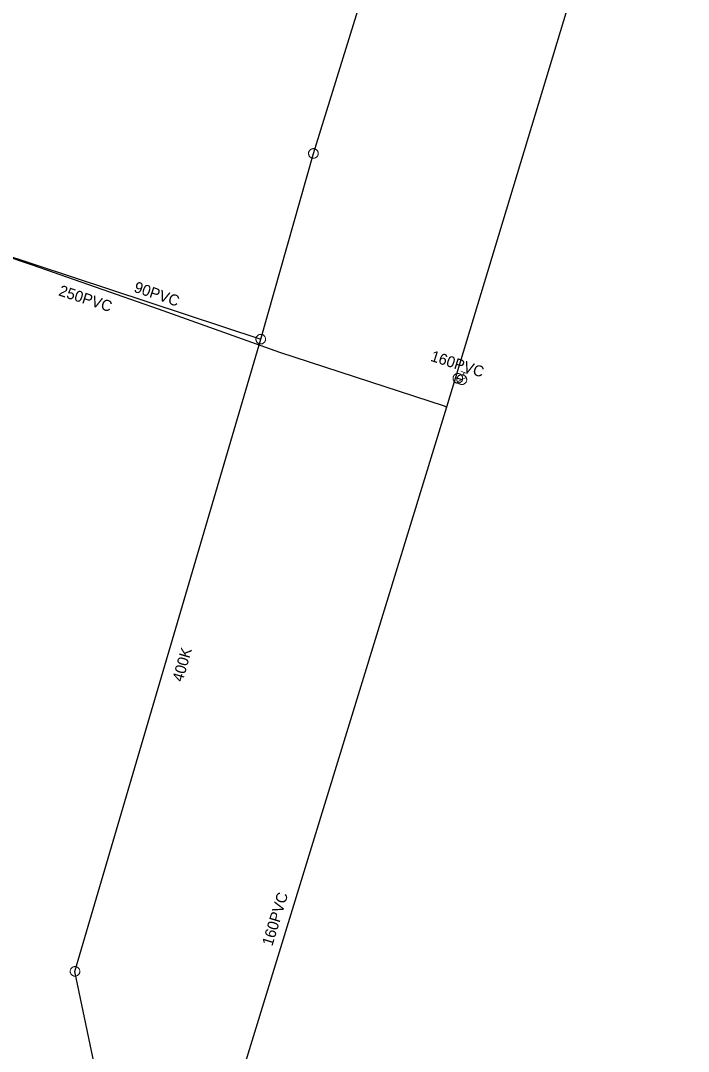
# Model space of a CAD drawing. Extents: x -741806 to -738704, y -1059275 to -1055387.
# Drawn here: x -740418.1 to -740357.3, y -1057228.9 to -1057135.1 of the extents above; entities that cross this region are included whole.
import ezdxf

# ---------------------------------------------------------------- set-up
doc = ezdxf.new("R2010")
doc.units = 0
doc.header["$LTSCALE"] = 0.4
for name, color, linetype, lineweight in [('2', 7, 'Continuous', 25), ('3', 7, 'Continuous', 13), ('50', 7, 'Continuous', 13), ('51', 7, 'Continuous', 13), ('52', 7, 'Continuous', 25)]:
    doc.layers.add(name, color=color, linetype=linetype, lineweight=lineweight)
doc.layers.add('5', color=7, linetype='Continuous')
doc.layers.add('53', color=7, linetype='Continuous')

msp = doc.modelspace()

# ---------------------------------------------------------------- linework, layer by layer
at = {"layer": '2'}
msp.add_line((-740426.199, -1057154.2), (-740396.239, -1057164.08), dxfattribs=at)
for points in [[(-740396.239, -1057164.08), (-740391.449, -1057147.19), (-740376.449, -1057098.879), (-740361.75, -1057051.12), (-740346.756, -1057003.12), (-740332.78, -1056960.44)], [(-740415.289, -1057258.669), (-740409.359, -1057239.62), (-740413.129, -1057221.58), (-740396.239, -1057164.08)]]:
    msp.add_lwpolyline(points, dxfattribs=at)
at = {"layer": '3'}
for points in [[(-740391.329, -1057146.768), (-740391.373, -1057146.759), (-740391.418, -1057146.753), (-740391.464, -1057146.753), (-740391.509, -1057146.757), (-740391.554, -1057146.766), (-740391.599, -1057146.779), (-740391.64, -1057146.797), (-740391.681, -1057146.819), (-740391.718, -1057146.846), (-740391.752, -1057146.876), (-740391.783, -1057146.91), (-740391.811, -1057146.946), (-740391.834, -1057146.986), (-740391.854, -1057147.027), (-740391.868, -1057147.07), (-740391.879, -1057147.115), (-740391.884, -1057147.161), (-740391.885, -1057147.206), (-740391.88, -1057147.252), (-740391.871, -1057147.297), (-740391.858, -1057147.341), (-740391.84, -1057147.382), (-740391.818, -1057147.423), (-740391.792, -1057147.46), (-740391.761, -1057147.495), (-740391.727, -1057147.525), (-740391.691, -1057147.553), (-740391.651, -1057147.577), (-740391.61, -1057147.596), (-740391.566, -1057147.61), (-740391.522, -1057147.621), (-740391.477, -1057147.626), (-740391.431, -1057147.627), (-740391.385, -1057147.622), (-740391.341, -1057147.614), (-740391.296, -1057147.601), (-740391.255, -1057147.582), (-740391.214, -1057147.56), (-740391.178, -1057147.533), (-740391.143, -1057147.504), (-740391.112, -1057147.47), (-740391.084, -1057147.433), (-740391.06, -1057147.394), (-740391.041, -1057147.353), (-740391.027, -1057147.309), (-740391.016, -1057147.264), (-740391.01, -1057147.219), (-740391.01, -1057147.174), (-740391.015, -1057147.128), (-740391.024, -1057147.082), (-740391.037, -1057147.039), (-740391.054, -1057146.997), (-740391.077, -1057146.957), (-740391.103, -1057146.919), (-740391.134, -1057146.885), (-740391.168, -1057146.853), (-740391.204, -1057146.827), (-740391.244, -1057146.803), (-740391.285, -1057146.784), (-740391.328, -1057146.769)], [(-740396.115, -1057163.659), (-740396.159, -1057163.65), (-740396.204, -1057163.644), (-740396.25, -1057163.642), (-740396.295, -1057163.646), (-740396.34, -1057163.655), (-740396.385, -1057163.668), (-740396.427, -1057163.686), (-740396.467, -1057163.707), (-740396.504, -1057163.734), (-740396.539, -1057163.763), (-740396.571, -1057163.796), (-740396.599, -1057163.833), (-740396.622, -1057163.872), (-740396.642, -1057163.913), (-740396.657, -1057163.956), (-740396.668, -1057164.001), (-740396.673, -1057164.047), (-740396.675, -1057164.092), (-740396.671, -1057164.138), (-740396.662, -1057164.183), (-740396.649, -1057164.227), (-740396.632, -1057164.268), (-740396.61, -1057164.309), (-740396.584, -1057164.347), (-740396.554, -1057164.382), (-740396.52, -1057164.413), (-740396.485, -1057164.441), (-740396.445, -1057164.465), (-740396.404, -1057164.484), (-740396.36, -1057164.499), (-740396.316, -1057164.51), (-740396.271, -1057164.516), (-740396.225, -1057164.517), (-740396.179, -1057164.513), (-740396.135, -1057164.505), (-740396.09, -1057164.492), (-740396.048, -1057164.474), (-740396.008, -1057164.452), (-740395.971, -1057164.426), (-740395.936, -1057164.397), (-740395.904, -1057164.363), (-740395.876, -1057164.327), (-740395.852, -1057164.288), (-740395.833, -1057164.247), (-740395.818, -1057164.203), (-740395.807, -1057164.158), (-740395.801, -1057164.113), (-740395.8, -1057164.068), (-740395.804, -1057164.022), (-740395.813, -1057163.976), (-740395.826, -1057163.933), (-740395.843, -1057163.89), (-740395.865, -1057163.85), (-740395.891, -1057163.813), (-740395.921, -1057163.778), (-740395.955, -1057163.746), (-740395.99, -1057163.719), (-740396.03, -1057163.695), (-740396.071, -1057163.675), (-740396.114, -1057163.66)], [(-740413.218, -1057221.151), (-740413.261, -1057221.163), (-740413.304, -1057221.179), (-740413.345, -1057221.2), (-740413.383, -1057221.224), (-740413.419, -1057221.253), (-740413.452, -1057221.285), (-740413.48, -1057221.321), (-740413.506, -1057221.359), (-740413.526, -1057221.4), (-740413.543, -1057221.442), (-740413.555, -1057221.487), (-740413.563, -1057221.532), (-740413.565, -1057221.578), (-740413.563, -1057221.623), (-740413.556, -1057221.669), (-740413.544, -1057221.713), (-740413.527, -1057221.756), (-740413.508, -1057221.797), (-740413.482, -1057221.835), (-740413.453, -1057221.871), (-740413.421, -1057221.903), (-740413.386, -1057221.932), (-740413.347, -1057221.957), (-740413.307, -1057221.978), (-740413.264, -1057221.995), (-740413.22, -1057222.006), (-740413.175, -1057222.014), (-740413.129, -1057222.017), (-740413.083, -1057222.014), (-740413.038, -1057222.007), (-740412.994, -1057221.996), (-740412.951, -1057221.98), (-740412.91, -1057221.959), (-740412.871, -1057221.933), (-740412.836, -1057221.906), (-740412.803, -1057221.873), (-740412.775, -1057221.838), (-740412.749, -1057221.799), (-740412.729, -1057221.759), (-740412.712, -1057221.716), (-740412.7, -1057221.672), (-740412.692, -1057221.626), (-740412.689, -1057221.581), (-740412.692, -1057221.535), (-740412.699, -1057221.49), (-740412.711, -1057221.445), (-740412.727, -1057221.403), (-740412.747, -1057221.362), (-740412.773, -1057221.323), (-740412.802, -1057221.288), (-740412.834, -1057221.255), (-740412.869, -1057221.226), (-740412.908, -1057221.201), (-740412.948, -1057221.18), (-740412.991, -1057221.164), (-740413.036, -1057221.151), (-740413.08, -1057221.144), (-740413.126, -1057221.142), (-740413.172, -1057221.144), (-740413.217, -1057221.15)]]:
    msp.add_lwpolyline(points, dxfattribs=at)
at = {"layer": '50'}
for p, q in [((-740378.027, -1057167.004), (-740377.735, -1057167.1)), ((-740377.812, -1057167.338), (-740377.735, -1057167.1)), ((-740377.443, -1057167.195), (-740377.735, -1057167.1)), ((-740377.95, -1057167.764), (-740378.35, -1057167.967)), ((-740377.95, -1057167.764), (-740377.554, -1057167.565))]:
    msp.add_line(p, q, dxfattribs=at)
msp.add_lwpolyline([(-740377.529, -1057167.905), (-740377.517, -1057167.858), (-740377.507, -1057167.812), (-740377.505, -1057167.765), (-740377.508, -1057167.718), (-740377.514, -1057167.674), (-740377.527, -1057167.627), (-740377.543, -1057167.585), (-740377.564, -1057167.541), (-740377.588, -1057167.502), (-740377.619, -1057167.467), (-740377.651, -1057167.433), (-740377.686, -1057167.402), (-740377.726, -1057167.378), (-740377.768, -1057167.356), (-740377.81, -1057167.339), (-740377.855, -1057167.328), (-740377.899, -1057167.318), (-740377.947, -1057167.317), (-740377.994, -1057167.319), (-740378.042, -1057167.326), (-740378.086, -1057167.338), (-740378.13, -1057167.354), (-740378.171, -1057167.375), (-740378.21, -1057167.399), (-740378.248, -1057167.429), (-740378.281, -1057167.461), (-740378.31, -1057167.497), (-740378.338, -1057167.537), (-740378.357, -1057167.579), (-740378.377, -1057167.621), (-740378.389, -1057167.667), (-740378.395, -1057167.713), (-740378.398, -1057167.758), (-740378.397, -1057167.806), (-740378.389, -1057167.852), (-740378.378, -1057167.898), (-740378.361, -1057167.94), (-740378.341, -1057167.983), (-740378.314, -1057168.024), (-740378.286, -1057168.058), (-740378.252, -1057168.092), (-740378.216, -1057168.121), (-740378.179, -1057168.148), (-740378.135, -1057168.17), (-740378.092, -1057168.188), (-740378.048, -1057168.199), (-740378.001, -1057168.206), (-740377.954, -1057168.209), (-740377.908, -1057168.207), (-740377.861, -1057168.2), (-740377.817, -1057168.189), (-740377.772, -1057168.172), (-740377.731, -1057168.152), (-740377.692, -1057168.128), (-740377.656, -1057168.096), (-740377.621, -1057168.065), (-740377.591, -1057168.029), (-740377.568, -1057167.989), (-740377.546, -1057167.948)], close=True, dxfattribs=at)
at = {"layer": '51'}
msp.add_lwpolyline([(-740377.896, -1057167.776), (-740377.884, -1057167.733), (-740377.877, -1057167.688), (-740377.874, -1057167.641), (-740377.876, -1057167.597), (-740377.884, -1057167.551), (-740377.895, -1057167.506), (-740377.912, -1057167.464), (-740377.932, -1057167.423), (-740377.958, -1057167.385), (-740377.986, -1057167.349), (-740378.019, -1057167.317), (-740378.054, -1057167.287), (-740378.093, -1057167.262), (-740378.133, -1057167.242), (-740378.176, -1057167.225), (-740378.221, -1057167.213), (-740378.266, -1057167.206), (-740378.311, -1057167.204), (-740378.357, -1057167.206), (-740378.403, -1057167.214), (-740378.447, -1057167.226), (-740378.49, -1057167.241), (-740378.53, -1057167.263), (-740378.569, -1057167.287), (-740378.604, -1057167.316), (-740378.637, -1057167.349), (-740378.665, -1057167.384), (-740378.691, -1057167.423), (-740378.711, -1057167.463), (-740378.728, -1057167.506), (-740378.74, -1057167.55), (-740378.747, -1057167.595), (-740378.749, -1057167.641), (-740378.747, -1057167.686), (-740378.74, -1057167.732), (-740378.728, -1057167.777), (-740378.711, -1057167.819), (-740378.691, -1057167.86), (-740378.666, -1057167.898), (-740378.637, -1057167.933), (-740378.605, -1057167.966), (-740378.569, -1057167.996), (-740378.531, -1057168.02), (-740378.49, -1057168.041), (-740378.447, -1057168.057), (-740378.403, -1057168.07), (-740378.358, -1057168.076), (-740378.312, -1057168.079), (-740378.266, -1057168.076), (-740378.221, -1057168.069), (-740378.177, -1057168.057), (-740378.134, -1057168.042), (-740378.093, -1057168.02), (-740378.055, -1057167.996), (-740378.019, -1057167.967), (-740377.986, -1057167.934), (-740377.958, -1057167.899), (-740377.933, -1057167.86), (-740377.912, -1057167.819), (-740377.896, -1057167.777)], dxfattribs=at)
at = {"layer": '52'}
for p, q in [((-740378.526, -1057167.571), (-740377.949, -1057167.76)), ((-740379.353, -1057170.263), (-740407.857, -1057263.098))]:
    msp.add_line(p, q, dxfattribs=at)
for points in [[(-740316.568, -1056963.017), (-740325.5, -1056993.58), (-740333.225, -1057017.973), (-740378.526, -1057167.571), (-740379.354, -1057170.267)], [(-740379.357, -1057170.275), (-740379.52, -1057170.179), (-740394.51, -1057165.29), (-740405.539, -1057161.35), (-740416.989, -1057157.35), (-740425.129, -1057154.62), (-740426.48, -1057152.71), (-740439.809, -1057144.86), (-740456.771, -1057136.215), (-740457.511, -1057135.899), (-740457.85, -1057135.75)]]:
    msp.add_lwpolyline(points, dxfattribs=at)

# ---------------------------------------------------------------- texts
at = {"layer": '5'}
for s, rotation, p in [('250PVC', 342, (-740414.69, -1057160.085)), ('400K', 74, (-740403.342, -1057195.307))]:
    msp.add_text(s, height=1, rotation=rotation, dxfattribs=at).set_placement(p)
at = {"layer": '53'}
for s, rotation, p in [('90PVC ', 341, (-740407.847, -1057159.753)), ('160PVC', 342, (-740380.862, -1057166.037)), ('160PVC', 73, (-740395.188, -1057219.332))]:
    msp.add_text(s, height=1, rotation=rotation, dxfattribs=at).set_placement(p)

doc.saveas('drawing.dxf')
